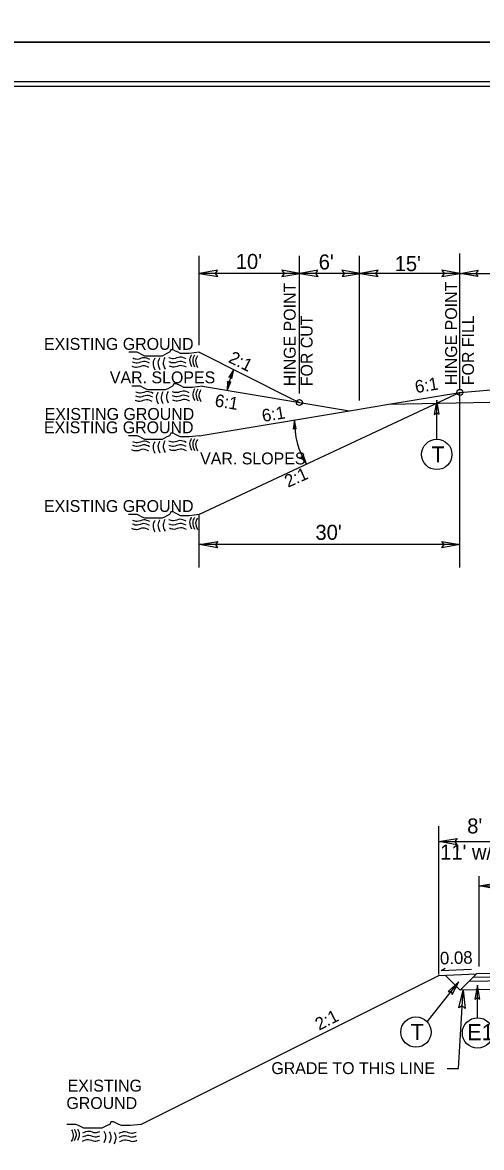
# Model space of a CAD drawing. Extents: x 573813 to 575363, y -54752 to -53123.
# Drawn here: x 574777.6 to 574829.6, y -53688.5 to -53560.8 of the extents above; entities that cross this region are included whole.
import ezdxf

# ---------------------------------------------------------------- set-up
doc = ezdxf.new("R2010")
doc.units = 0
for name, color, linetype in [('Old_Level_1', 7, 'Continuous'), ('Old_Level_11', 7, 'Continuous'), ('Old_Level_2', 7, 'Continuous'), ('Old_Level_3', 7, 'Continuous'), ('Prop Pavement Schedule Description CELL', 7, 'Continuous'), ('Sheet Cutting Line CELL', 7, 'Continuous'), ('Sheet Plot Border Inside CELL', 7, 'Continuous'), ('Sheet Plot Border Outside CELL', 7, 'Continuous'), ('Sheet Typical CELL', 7, 'Continuous'), ('Typical ID Circle CELL', 7, 'Continuous'), ('Typical Terminator CELL', 7, 'Continuous')]:
    doc.layers.add(name, color=color, linetype=linetype)

msp = doc.modelspace()

# ---------------------------------------------------------------- linework, layer by layer
at = {"layer": 'Old_Level_1'}
for p, q in [((574797.64, -53598.25), (574807.94, -53603.4)), ((574798.01, -53602.1), (574814.68, -53604.88)), ((574827.2, -53602.8), (574836.3, -53602.04)), ((574827.2, -53602.8), (574797.64, -53616.66)), ((574807.94, -53603.4), (574809.01, -53603.94)), ((574819.12, -53604.14), (574840.85, -53603.71)), ((574819.15, -53604.14), (574827.2, -53602.8)), ((574797.64, -53607.72), (574814.68, -53604.88)), ((574814.68, -53604.88), (574819.15, -53604.14)), ((574824.82, -53668.97), (574829.08, -53668.78)), ((574829.08, -53668.78), (574827.22, -53670.64)), ((574843.01, -53668.9), (574828.66, -53669.19)), ((574833.91, -53668.68), (574829.08, -53668.78)), ((574791.05, -53685.86), (574824.82, -53668.97)), ((574825.53, -53668.94), (574827.22, -53670.64)), ((574843.01, -53669.34), (574828.21, -53669.65)), ((574846.14, -53670.24), (574827.22, -53670.64))]:
    msp.add_line(p, q, dxfattribs=at)
for points in [[(574797.64, -53598.25), (574796.52, -53598.39), (574796.24, -53598.39), (574795.82, -53598.39), (574795.54, -53598.39), (574795.26, -53598.25), (574794.98, -53598.11), (574794.7, -53597.97), (574794.42, -53597.97), (574794.28, -53598.25), (574794, -53598.39), (574793.72, -53598.53), (574793.44, -53598.67), (574793.16, -53598.67), (574792.88, -53598.67), (574792.6, -53598.67), (574792.32, -53598.67), (574792.04, -53598.67), (574791.76, -53598.67), (574791.48, -53598.67), (574791.2, -53598.53), (574790.92, -53598.39), (574790.64, -53598.25), (574790.22, -53598.25), (574789.94, -53598.25), (574789.66, -53598.25)], [(574798.01, -53602.1), (574796.89, -53602.24), (574796.61, -53602.24), (574796.19, -53602.24), (574795.91, -53602.24), (574795.63, -53602.1), (574795.34, -53601.96), (574795.06, -53601.82), (574794.78, -53601.82), (574794.64, -53602.1), (574794.36, -53602.24), (574794.08, -53602.38), (574793.8, -53602.52), (574793.52, -53602.52), (574793.24, -53602.52), (574792.96, -53602.52), (574792.68, -53602.52), (574792.4, -53602.52), (574792.12, -53602.52), (574791.84, -53602.52), (574791.56, -53602.38), (574791.28, -53602.24), (574791, -53602.1), (574790.58, -53602.1), (574790.3, -53602.1), (574790.02, -53602.1)], [(574797.64, -53607.72), (574796.52, -53607.86), (574796.24, -53607.86), (574795.82, -53607.86), (574795.54, -53607.86), (574795.26, -53607.72), (574794.98, -53607.58), (574794.7, -53607.44), (574794.42, -53607.44), (574794.28, -53607.72), (574794, -53607.86), (574793.72, -53608), (574793.44, -53608.14), (574793.16, -53608.14), (574792.88, -53608.14), (574792.6, -53608.14), (574792.32, -53608.14), (574792.04, -53608.14), (574791.76, -53608.14), (574791.48, -53608.14), (574791.2, -53608), (574790.92, -53607.86), (574790.64, -53607.72), (574790.22, -53607.72), (574789.93, -53607.72), (574789.65, -53607.72)], [(574797.64, -53616.66), (574796.52, -53616.79), (574796.24, -53616.79), (574795.82, -53616.79), (574795.54, -53616.79), (574795.26, -53616.66), (574794.98, -53616.51), (574794.7, -53616.37), (574794.42, -53616.37), (574794.28, -53616.66), (574794, -53616.79), (574793.72, -53616.94), (574793.44, -53617.07), (574793.16, -53617.07), (574792.88, -53617.07), (574792.6, -53617.07), (574792.32, -53617.07), (574792.04, -53617.07), (574791.76, -53617.07), (574791.48, -53617.07), (574791.2, -53616.94), (574790.92, -53616.79), (574790.64, -53616.66), (574790.21, -53616.66), (574789.93, -53616.66), (574789.65, -53616.66)], [(574791.05, -53685.86), (574789.87, -53686), (574789.57, -53686), (574789.13, -53686), (574788.83, -53686), (574788.54, -53685.86), (574788.24, -53685.71), (574787.95, -53685.56), (574787.65, -53685.56), (574787.51, -53685.86), (574787.21, -53686), (574786.92, -53686.15), (574786.62, -53686.3), (574786.33, -53686.3), (574786.03, -53686.3), (574785.74, -53686.3), (574785.44, -53686.3), (574785.15, -53686.3), (574784.85, -53686.3), (574784.56, -53686.3), (574784.26, -53686.15), (574783.97, -53686), (574783.67, -53685.86), (574783.23, -53685.86), (574782.93, -53685.86), (574782.64, -53685.86)]]:
    msp.add_lwpolyline(points, dxfattribs=at)
for centre in [(574827.2, -53602.8), (574809.01, -53603.94)]:
    msp.add_circle(centre, 0.338, dxfattribs=at)
for centre, start, end in [((574809.49, -53604.07), 153.9334, 170.1878), ((574817.26, -53606.26), 177.8236, 212.181)]:
    msp.add_arc(centre, 8.8, start, end, dxfattribs=at)
at = {"layer": 'Old_Level_11'}
for p, q in [((574827.2, -53602.4), (574827.2, -53587.03)), ((574797.64, -53597.44), (574797.64, -53587.31)), ((574809.01, -53602.93), (574809.01, -53587.31)), ((574815.83, -53603.71), (574815.83, -53587.31)), ((574827.2, -53602.55), (574827.2, -53587.31)), ((574809.07, -53589.29), (574797.7, -53589.29)), ((574815.89, -53589.29), (574809.06, -53589.29)), ((574827.26, -53589.29), (574815.89, -53589.29)), ((574827.2, -53589.29), (574840.85, -53589.29)), ((574827.2, -53622.68), (574827.2, -53602.8)), ((574797.64, -53622.68), (574797.64, -53616.66)), ((574827.2, -53620.07), (574797.7, -53620.07)), ((574824.82, -53668.85), (574824.82, -53652.04)), ((574824.82, -53653.78), (574833.91, -53653.78)), ((574829.37, -53667.95), (574829.37, -53657.68)), ((574829.37, -53658.81), (574833.91, -53658.81)), ((574827.03, -53679.52), (574827.57, -53670.63)), ((574825.75, -53679.52), (574827.03, -53679.52))]:
    msp.add_line(p, q, dxfattribs=at)
for points in [[(574799.74, -53588.94), (574797.7, -53589.29), (574799.75, -53589.65), (574799.49, -53589.29)], [(574807.02, -53589.64), (574809.06, -53589.29), (574807.01, -53588.93), (574807.27, -53589.29)], [(574811.11, -53588.94), (574809.06, -53589.29), (574811.12, -53589.65), (574810.86, -53589.29)], [(574813.84, -53589.64), (574815.89, -53589.29), (574813.83, -53588.93), (574814.09, -53589.29)], [(574817.93, -53588.94), (574815.89, -53589.29), (574817.94, -53589.65), (574817.68, -53589.29)], [(574825.16, -53589.64), (574827.2, -53589.29), (574825.14, -53588.92), (574825.41, -53589.29)], [(574829.25, -53589.64), (574827.2, -53589.29), (574829.26, -53588.92), (574829, -53589.29)], [(574801.34, -53601.22), (574801.59, -53600.21), (574801.01, -53601.08), (574801.23, -53601.03)], [(574800.88, -53601.54), (574800.82, -53602.57), (574801.23, -53601.61), (574801.03, -53601.7)], [(574808.65, -53606.95), (574808.46, -53605.93), (574808.29, -53606.96), (574808.47, -53606.83)], [(574809.17, -53610.13), (574809.81, -53610.95), (574809.48, -53609.96), (574809.38, -53610.16)], [(574799.74, -53620.42), (574797.7, -53620.07), (574799.75, -53619.71), (574799.49, -53620.07)], [(574825.16, -53619.72), (574827.2, -53620.07), (574825.14, -53620.43), (574825.41, -53620.07)], [(574826.86, -53654.13), (574824.82, -53653.78), (574826.88, -53653.41), (574826.61, -53653.78)], [(574831.41, -53659.16), (574829.37, -53658.81), (574831.42, -53658.44), (574831.16, -53658.81)], [(574827.09, -53672.65), (574827.57, -53670.63), (574827.81, -53672.71), (574827.46, -53672.42)]]:
    msp.add_lwpolyline(points, close=True, dxfattribs=at)
at = {"layer": 'Old_Level_2'}
for q in [(574825.54, -53668.13), (574828.52, -53668.26)]:
    msp.add_line((574825.09, -53668.42), q, dxfattribs=at)
for points in [[(574796.76, -53598.55), (574796.57, -53599.12), (574796.77, -53599.87)], [(574796.76, -53598.55), (574796.57, -53599.12), (574796.77, -53599.87)], [(574797.11, -53598.59), (574796.92, -53599.16), (574797.13, -53599.91)], [(574797.11, -53598.59), (574796.92, -53599.16), (574797.13, -53599.91)], [(574797.45, -53598.66), (574797.25, -53599.22), (574797.46, -53599.97)], [(574797.45, -53598.66), (574797.25, -53599.22), (574797.46, -53599.97)], [(574791.96, -53599.98), (574791.28, -53599.79), (574790.56, -53599.97), (574790.04, -53599.86)], [(574791.96, -53599.98), (574791.28, -53599.79), (574790.56, -53599.97), (574790.04, -53599.86)], [(574792.03, -53599.49), (574791.35, -53599.29), (574790.63, -53599.48), (574790.1, -53599.36)], [(574792.03, -53599.49), (574791.35, -53599.29), (574790.63, -53599.48), (574790.1, -53599.36)], [(574792.05, -53599.06), (574791.37, -53598.86), (574790.65, -53599.05), (574790.12, -53598.93)], [(574792.05, -53599.06), (574791.37, -53598.86), (574790.65, -53599.05), (574790.12, -53598.93)], [(574792.62, -53598.93), (574792.42, -53599.49), (574792.63, -53600.24)], [(574792.62, -53598.93), (574792.42, -53599.49), (574792.63, -53600.24)], [(574793.17, -53598.88), (574792.98, -53599.45), (574793.18, -53600.19)], [(574793.17, -53598.88), (574792.98, -53599.45), (574793.18, -53600.19)], [(574793.76, -53598.83), (574793.57, -53599.4), (574793.78, -53600.15)], [(574793.76, -53598.83), (574793.57, -53599.4), (574793.78, -53600.15)], [(574796.16, -53599), (574795.47, -53598.8), (574794.75, -53598.98), (574794.23, -53598.87)], [(574796.16, -53599), (574795.47, -53598.8), (574794.75, -53598.98), (574794.23, -53598.87)], [(574796.16, -53599.47), (574795.47, -53599.28), (574794.75, -53599.46), (574794.23, -53599.34)], [(574796.16, -53599.47), (574795.47, -53599.28), (574794.75, -53599.46), (574794.23, -53599.34)], [(574796.21, -53599.95), (574795.53, -53599.76), (574794.8, -53599.94), (574794.28, -53599.82)], [(574796.21, -53599.95), (574795.53, -53599.76), (574794.8, -53599.94), (574794.28, -53599.82)], [(574797.13, -53602.4), (574796.93, -53602.97), (574797.14, -53603.72)], [(574797.13, -53602.4), (574796.93, -53602.97), (574797.14, -53603.72)], [(574797.48, -53602.44), (574797.29, -53603.01), (574797.5, -53603.76)], [(574797.48, -53602.44), (574797.29, -53603.01), (574797.5, -53603.76)], [(574797.81, -53602.51), (574797.62, -53603.07), (574797.83, -53603.82)], [(574797.81, -53602.51), (574797.62, -53603.07), (574797.83, -53603.82)], [(574792.33, -53603.84), (574791.64, -53603.64), (574790.92, -53603.82), (574790.4, -53603.71)], [(574792.33, -53603.84), (574791.64, -53603.64), (574790.92, -53603.82), (574790.4, -53603.71)], [(574792.4, -53603.34), (574791.71, -53603.14), (574790.99, -53603.33), (574790.47, -53603.21)], [(574792.4, -53603.34), (574791.71, -53603.14), (574790.99, -53603.33), (574790.47, -53603.21)], [(574792.42, -53602.91), (574791.73, -53602.71), (574791.01, -53602.9), (574790.49, -53602.78)], [(574792.42, -53602.91), (574791.73, -53602.71), (574791.01, -53602.9), (574790.49, -53602.78)], [(574792.98, -53602.78), (574792.79, -53603.35), (574793, -53604.09)], [(574792.98, -53602.78), (574792.79, -53603.35), (574793, -53604.09)], [(574793.53, -53602.73), (574793.34, -53603.3), (574793.55, -53604.05)], [(574793.53, -53602.73), (574793.34, -53603.3), (574793.55, -53604.05)], [(574794.13, -53602.68), (574793.94, -53603.25), (574794.14, -53604)], [(574794.13, -53602.68), (574793.94, -53603.25), (574794.14, -53604)], [(574796.52, -53602.85), (574795.84, -53602.65), (574795.11, -53602.83), (574794.6, -53602.72)], [(574796.52, -53602.85), (574795.84, -53602.65), (574795.11, -53602.83), (574794.6, -53602.72)], [(574796.53, -53603.32), (574795.84, -53603.13), (574795.12, -53603.31), (574794.6, -53603.19)], [(574796.53, -53603.32), (574795.84, -53603.13), (574795.12, -53603.31), (574794.6, -53603.19)], [(574796.58, -53603.8), (574795.89, -53603.61), (574795.17, -53603.79), (574794.65, -53603.67)], [(574796.58, -53603.8), (574795.89, -53603.61), (574795.17, -53603.79), (574794.65, -53603.67)], [(574792.03, -53608.96), (574791.35, -53608.76), (574790.63, -53608.95), (574790.1, -53608.83)], [(574792.03, -53608.96), (574791.35, -53608.76), (574790.63, -53608.95), (574790.1, -53608.83)], [(574792.05, -53608.53), (574791.36, -53608.34), (574790.64, -53608.52), (574790.12, -53608.4)], [(574792.05, -53608.53), (574791.36, -53608.34), (574790.64, -53608.52), (574790.12, -53608.4)], [(574792.62, -53608.4), (574792.42, -53608.97), (574792.63, -53609.71)], [(574792.62, -53608.4), (574792.42, -53608.97), (574792.63, -53609.71)], [(574793.17, -53608.35), (574792.98, -53608.92), (574793.18, -53609.67)], [(574793.17, -53608.35), (574792.98, -53608.92), (574793.18, -53609.67)], [(574793.76, -53608.3), (574793.57, -53608.87), (574793.78, -53609.62)], [(574793.76, -53608.3), (574793.57, -53608.87), (574793.78, -53609.62)], [(574796.16, -53608.47), (574795.47, -53608.27), (574794.75, -53608.45), (574794.23, -53608.34)], [(574796.16, -53608.47), (574795.47, -53608.27), (574794.75, -53608.45), (574794.23, -53608.34)], [(574796.16, -53608.94), (574795.47, -53608.75), (574794.75, -53608.93), (574794.23, -53608.81)], [(574796.16, -53608.94), (574795.47, -53608.75), (574794.75, -53608.93), (574794.23, -53608.81)], [(574796.76, -53608.03), (574796.57, -53608.59), (574796.77, -53609.34)], [(574796.76, -53608.03), (574796.57, -53608.59), (574796.77, -53609.34)], [(574797.11, -53608.06), (574796.92, -53608.63), (574797.13, -53609.38)], [(574797.11, -53608.06), (574796.92, -53608.63), (574797.13, -53609.38)], [(574797.45, -53608.13), (574797.25, -53608.69), (574797.46, -53609.44)], [(574797.45, -53608.13), (574797.25, -53608.69), (574797.46, -53609.44)], [(574791.96, -53609.46), (574791.28, -53609.26), (574790.56, -53609.45), (574790.03, -53609.33)], [(574791.96, -53609.46), (574791.28, -53609.26), (574790.56, -53609.45), (574790.03, -53609.33)], [(574796.21, -53609.42), (574795.53, -53609.23), (574794.8, -53609.41), (574794.28, -53609.29)], [(574796.21, -53609.42), (574795.53, -53609.23), (574794.8, -53609.41), (574794.28, -53609.29)], [(574792.03, -53617.89), (574791.35, -53617.69), (574790.63, -53617.88), (574790.1, -53617.76)], [(574792.03, -53617.89), (574791.35, -53617.69), (574790.63, -53617.88), (574790.1, -53617.76)], [(574792.05, -53617.46), (574791.36, -53617.27), (574790.64, -53617.45), (574790.12, -53617.33)], [(574792.05, -53617.46), (574791.36, -53617.27), (574790.64, -53617.45), (574790.12, -53617.33)], [(574792.62, -53617.33), (574792.42, -53617.9), (574792.63, -53618.64)], [(574792.62, -53617.33), (574792.42, -53617.9), (574792.63, -53618.64)], [(574793.17, -53617.28), (574792.98, -53617.85), (574793.18, -53618.6)], [(574793.17, -53617.28), (574792.98, -53617.85), (574793.18, -53618.6)], [(574793.76, -53617.24), (574793.57, -53617.8), (574793.78, -53618.55)], [(574793.76, -53617.24), (574793.57, -53617.8), (574793.78, -53618.55)], [(574796.16, -53617.4), (574795.47, -53617.2), (574794.75, -53617.38), (574794.23, -53617.27)], [(574796.16, -53617.4), (574795.47, -53617.2), (574794.75, -53617.38), (574794.23, -53617.27)], [(574796.16, -53617.87), (574795.47, -53617.68), (574794.75, -53617.86), (574794.23, -53617.75)], [(574796.16, -53617.87), (574795.47, -53617.68), (574794.75, -53617.86), (574794.23, -53617.75)], [(574796.76, -53616.96), (574796.57, -53617.52), (574796.77, -53618.27)], [(574796.76, -53616.96), (574796.57, -53617.52), (574796.77, -53618.27)], [(574797.11, -53616.99), (574796.92, -53617.56), (574797.13, -53618.31)], [(574797.11, -53616.99), (574796.92, -53617.56), (574797.13, -53618.31)], [(574797.45, -53617.06), (574797.25, -53617.62), (574797.46, -53618.37)], [(574797.45, -53617.06), (574797.25, -53617.62), (574797.46, -53618.37)], [(574791.96, -53618.39), (574791.28, -53618.19), (574790.55, -53618.38), (574790.03, -53618.26)], [(574791.96, -53618.39), (574791.28, -53618.19), (574790.55, -53618.38), (574790.03, -53618.26)], [(574796.21, -53618.35), (574795.53, -53618.16), (574794.8, -53618.34), (574794.28, -53618.22)], [(574796.21, -53618.35), (574795.53, -53618.16), (574794.8, -53618.34), (574794.28, -53618.22)], [(574783.18, -53686.47), (574783.37, -53687.04), (574783.16, -53687.79)], [(574783.18, -53686.47), (574783.37, -53687.04), (574783.16, -53687.79)], [(574783.51, -53686.41), (574783.7, -53686.98), (574783.49, -53687.73)], [(574783.51, -53686.41), (574783.7, -53686.98), (574783.49, -53687.73)], [(574783.86, -53686.37), (574784.06, -53686.94), (574783.85, -53687.69)], [(574783.86, -53686.37), (574784.06, -53686.94), (574783.85, -53687.69)], [(574784.47, -53686.81), (574785.15, -53686.62), (574785.87, -53686.8), (574786.39, -53686.68)], [(574784.47, -53686.81), (574785.15, -53686.62), (574785.87, -53686.8), (574786.39, -53686.68)], [(574786.86, -53686.65), (574787.05, -53687.22), (574786.84, -53687.96)], [(574786.86, -53686.65), (574787.05, -53687.22), (574786.84, -53687.96)], [(574787.45, -53686.7), (574787.65, -53687.26), (574787.44, -53688.01)], [(574787.45, -53686.7), (574787.65, -53687.26), (574787.44, -53688.01)], [(574788.01, -53686.75), (574788.2, -53687.31), (574787.99, -53688.06)], [(574788.01, -53686.75), (574788.2, -53687.31), (574787.99, -53688.06)], [(574788.57, -53686.88), (574789.26, -53686.68), (574789.98, -53686.87), (574790.5, -53686.75)], [(574788.57, -53686.88), (574789.26, -53686.68), (574789.98, -53686.87), (574790.5, -53686.75)], [(574784.41, -53687.77), (574785.09, -53687.58), (574785.82, -53687.76), (574786.34, -53687.64)], [(574784.41, -53687.77), (574785.09, -53687.58), (574785.82, -53687.76), (574786.34, -53687.64)], [(574784.46, -53687.29), (574785.15, -53687.1), (574785.87, -53687.28), (574786.39, -53687.16)], [(574784.46, -53687.29), (574785.15, -53687.1), (574785.87, -53687.28), (574786.39, -53687.16)], [(574788.59, -53687.31), (574789.28, -53687.11), (574790, -53687.3), (574790.52, -53687.18)], [(574788.59, -53687.31), (574789.28, -53687.11), (574790, -53687.3), (574790.52, -53687.18)], [(574788.66, -53687.8), (574789.34, -53687.61), (574790.07, -53687.79), (574790.59, -53687.67)], [(574788.66, -53687.8), (574789.34, -53687.61), (574790.07, -53687.79), (574790.59, -53687.67)]]:
    msp.add_spline(points, degree=3, dxfattribs=at)
at = {"layer": 'Sheet Cutting Line CELL'}
for p, q in [((575006.71, -53563.07), (574669.73, -53563.07)), ((574669.73, -53563.07), (575006.71, -53563.07))]:
    msp.add_line(p, q, dxfattribs=at)
at = {"layer": 'Sheet Plot Border Inside CELL'}
msp.add_lwpolyline([(575005.81, -53567.56), (574672.33, -53567.56), (574672.33, -53778.7), (575005.81, -53778.7)], close=True, dxfattribs=at)
at = {"layer": 'Sheet Plot Border Outside CELL'}
for p, q in [((574669.73, -53563.07), (575006.71, -53563.07)), ((575006.71, -53563.07), (574669.73, -53563.07))]:
    msp.add_line(p, q, dxfattribs=at)
for points in [[(575006.71, -53342.95), (574669.73, -53342.95), (574669.73, -53563.07), (575006.71, -53563.07)], [(575006.71, -53563.07), (574669.73, -53563.07), (574669.73, -53783.19), (575006.71, -53783.19)]]:
    msp.add_lwpolyline(points, close=True, dxfattribs=at)
at = {"layer": 'Sheet Typical CELL'}
msp.add_lwpolyline([(575003.31, -53568.07), (574703.15, -53568.07), (574703.15, -53778.19), (575003.31, -53778.19)], close=True, dxfattribs=at)
at = {"layer": 'Typical ID Circle CELL'}
for p, q in [((574824.58, -53608.13), (574824.58, -53603.69)), ((574823.48, -53674.22), (574827.09, -53669.69)), ((574829.19, -53673.77), (574829.19, -53670.11))]:
    msp.add_line(p, q, dxfattribs=at)
for centre in [(574824.58, -53609.84), (574822.22, -53675.39), (574829.2, -53675.49)]:
    msp.add_circle(centre, 1.72, dxfattribs=at)
at = {"layer": 'Typical Terminator CELL'}
for points in [[(574824.85, -53605.28), (574824.58, -53603.69), (574824.3, -53605.29), (574824.58, -53605.08)], [(574826.31, -53671.11), (574827.09, -53669.69), (574825.87, -53670.77), (574826.22, -53670.78)], [(574829.47, -53671.66), (574829.19, -53670.07), (574828.91, -53671.67), (574829.19, -53671.46)]]:
    msp.add_lwpolyline(points, close=True, dxfattribs=at)

# ---------------------------------------------------------------- texts
at = {"layer": 'Old_Level_1'}
for s, height, rotation, p in [('HINGE POINT', 1.3502, 90, (574808.59, -53602.1)), ('HINGE POINT', 1.3502, 90, (574826.88, -53601.98)), ('FOR CUT ', 1.35, 90, (574810.51, -53602.1)), ('FOR FILL', 1.35, 90, (574828.8, -53601.98)), ('EXISTING GROUND', 1.3502, 0, (574780.06, -53597.97)), ('2:1', 1.421, 333.435, (574800.87, -53599.32)), ('VAR. SLOPES', 1.3502, 0, (574787.53, -53601.77)), ('6:1', 1.421, 9.4624, (574822.23, -53602.89)), ('6:1', 1.421, 350.5376, (574799.35, -53604.37)), ('EXISTING GROUND', 1.3502, 0, (574780.14, -53605.92)), ('6:1', 1.421, 9.1472, (574804.88, -53606.16)), ('EXISTING GROUND', 1.3502, 0, (574780.06, -53607.44)), ('VAR. SLOPES', 1.3502, 0, (574797.76, -53610.97)), ('2:1', 1.421, 24.2424, (574807.72, -53613.63)), ('EXISTING GROUND', 1.3502, 0, (574780.06, -53616.37)), ('0.08', 1.421, 1.6633, (574824.96, -53667.72)), ('2:1', 1.421, 27.0855, (574811.25, -53675.24)), ('EXISTING', 1.35, 360, (574782.74, -53682.14)), ('GROUND', 1.35, 360, (574782.6, -53684.12))]:
    msp.add_text(s, height=height, rotation=rotation, dxfattribs=at).set_placement(p)
at = {"layer": 'Old_Level_11'}
for s, height, rotation, p in [("10'", 1.705, 0, (574801.8, -53588.79)), ("6'", 1.705, 0, (574811.2, -53588.85)), ("15'", 1.705, 0, (574819.81, -53589.04)), ("30'", 1.705, 360, (574810.83, -53619.53)), ('GRADE TO THIS LINE', 1.3502, 360, (574805.83, -53680.16))]:
    msp.add_text(s, height=height, rotation=rotation, dxfattribs=at).set_placement(p)
at = {"layer": 'Old_Level_3'}
for s, p in [("8'", (574828.03, -53652.85)), ("11' w/ GR", (574824.96, -53655.81))]:
    msp.add_text(s, height=1.705, rotation=359.8329, dxfattribs=at).set_placement(p)
at = {"layer": 'Prop Pavement Schedule Description CELL'}
for p in [(574823.98, -53610.75), (574821.62, -53676.3)]:
    msp.add_text('T', height=1.82, rotation=360, dxfattribs=at).set_placement(p)
msp.add_text('E1', height=1.819, dxfattribs=at).set_placement((574828.05, -53676.31))

doc.saveas('drawing.dxf')
